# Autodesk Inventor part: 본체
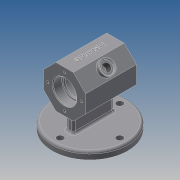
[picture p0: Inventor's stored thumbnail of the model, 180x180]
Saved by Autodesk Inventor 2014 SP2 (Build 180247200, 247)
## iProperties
Created: 2021-02
Part Number: 본체
Material: Generic
Document SubType Name: Modeling
Designer: kb542-10
Density: 1 g/cm^3
Appearance: Default
Author: kb542-10
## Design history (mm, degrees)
sketch "스케치1"
  geometry: L1 (11.995, -29.007)-(-12.03, -28.993); L2 (-12.03, -28.993)-(-29.007, -11.995); L3 (-29.007, -11.995)-(-28.993, 12.03); L4 (-28.993, 12.03)-(-11.995, 29.007); L5 (-11.995, 29.007)-(12.03, 28.993); L6 (12.03, 28.993)-(29.007, 11.995); L7 (29.007, 11.995)-(28.993, -12.03); L8 (28.993, -12.03)-(11.995, -29.007); 2 further points
  constraints: 16 end point, 1 coincident, 17 other
  dimensions: "d0" = 58 distance between parallel lines of L8 L4
extrude "돌출1" new body sketch "스케치1" stored distance "d1" = 70; taper "d2" = 0 deg
sketch "스케치2"
  geometry: L1 (12.03, 35)-(-11.995, 35) reference; L2 (-11.995, -35)-(12.03, -35) reference; L3 (29.007, 35)-(29.007, -35) reference; L4 (-28.993, 35)-(-28.993, -35) reference; L5 (0.018, 35)-(0.018, -35); L6 (16.018, 35)-(16.018, 23); L7 (16.018, 23)-(14.018, 23); L8 (14.018, 23)-(14.018, 20); L9 (14.018, 20)-(22.018, 20); L10 (22.018, 20)-(22.018, -20); L11 (22.018, -20)-(14.018, -20); L12 (14.018, -20)-(14.018, -23); L13 (14.018, -23)-(16.018, -23); L14 (16.018, -23)-(16.018, -35); L15 (16.018, 35)-(0.018, 35); L16 (16.018, -35)-(0.018, -35); 1 further point
  constraints: 24 end point, 7 parallel, 3 collinear, 3 perpendicular, 2 midpoint, 2 point on line
  dimensions: "d3" = 44 diameter of L10 L5; "d4" = 32 diameter of L6 L5; "d5" = 28 diameter of L8 L5; "d6" = 12 distance of L6.start L6.end; "d7" = 12 distance of L13.end L14.end; "d8" = 3 distance of L7.end L8.end; "d9" = 3 distance of L11.end L12.end
revolve "회전1" sketch "스케치2" stored, may be unused: angle "d10" = 90 deg
node "작업 평면1"
sketch "스케치3"
  geometry: C1 r 52 at (0, 0); 1 further point
  constraints: 1 centre point, 1 coincident
  dimensions: "d12" = 104 diameter of C1
extrude "돌출2" join sketch "스케치3" distance "d13" = 10; taper "d14" = 0 deg
sketch "스케치4"
  geometry: L1 (0, 52)-(0, -52); L2 (52, 0)-(-52, 0); L3 (5, 28)-(-5, 28); L4 (-5, 28)-(-5, -28); L5 (-5, -28)-(5, -28); L6 (5, -28)-(5, 28); A1 r 52 centre (0, 0) between (0, 52) and (0, -52) reference; 4 further points
  constraints: 12 end point, 6 midpoint, 4 point on circle, 2 parallel, 2 perpendicular, 1 horizontal, 1 horizontal alignment, 1 vertical, 1 vertical alignment
  dimensions: "d15" = 10 distance between parallel lines of L4 L6; "d16" = 56 distance between parallel lines of L5 L3
extrude "돌출3" join sketch "스케치4" stored distance "d17" = 10; taper "d18" = 0 deg
sketch "스케치11"
  geometry: L1 (0, 16.988)-(70, 16.988) reference; C1 r 10 at (35, -12.012); 1 further point
  constraints: 1 centre point, 1 coincident
  dimensions: "d47" = 20 diameter of C1
extrude "돌출6" join sketch "스케치11" distance "d48" = 5; taper "d49" = 0 deg
sketch "스케치12"
  geometry: C1 r 10 at (0, 0) reference; C2 r 8 at (0, 0)
  constraints: 1 centre point, 1 coincident
  dimensions: "d50" = 16 diameter of C2
extrude "돌출7" cut sketch "스케치12" distance "d51" = 2; taper "d52" = 0 deg
sketch "스케치13"
  geometry: C1 r 8 at (0, 0) reference; 1 further point
  constraints: 1 coincident
hole "구멍3" sketch "스케치13" at (0, 0) diameter "d53" = 10.917; stored, may be unused: countersink angle "d57" = 90 deg, drill point angle "d59" = 118 deg; dims "d54" = 15, "d55" = 4, "d56" = 2, "d58" = 8
sketch "스케치8"
  geometry: L1 (5, 28)-(5, -28) reference; L2 (5, -28)-(-5, -28) reference; L3 (-52, 0)-(52, 0); L4 (0, 52)-(0, -52); A1 r 52 centre (0, 0) between (-52, 0) and (52, 0) reference; A2 r 41 centre (0, 0) between (0, 41) and (-41, 0); 4 further points
  constraints: 8 point on circle, 4 end point, 4 midpoint, 4 point on line, 2 parallel, 1 centre point, 1 coincident
  dimensions: "d27" = 82 diameter of A2
hole "구멍1" sketch "스케치8" at (0, 41), (-41, 0), (0, -41), (41, 0) diameter "d28" = 9; stored, may be unused: countersink angle "d32" = 90 deg, drill point angle "d34" = 118 deg; dims "d29" = 6, "d30" = 4, "d31" = 2, "d33" = 8
sketch "스케치14" dims "d65" = 46
  geometry: C1 r 16 at (0, 0.018) reference; 6 further points
  constraints: 1 coincident, 1 horizontal alignment, 8 other
  dimensions: "d68" = 360 deg dimension on C1.centre point (23, 0.018) (derived)
hole "구멍4" sketch "스케치14" at (23, 0.018), (0, 23.018), (-23, 0.018), (0, -22.982) diameter "d70" = 3.242; stored, may be unused: countersink angle "d74" = 90 deg, drill point angle "d76" = 118 deg; dims "d71" = 8, "d72" = 4, "d73" = 2, "d75" = 10
sketch "스케치10"
  geometry: L1 (24.024, 0)-(0, 0) reference; L2 (-16.988, 0)-(-16.988, 70) reference; 2 further points
  constraints: 1 other
  dimensions: "d42" = 35 distance from line of L1 point (12.012, 35); "d43" = 29 distance from line of point (12.012, 35) L2
feature "엠보싱1" sketch "스케치10" dims "d44" = 1, "d45" = 0
chamfer "모따기1" distance "d60" = 1; stored, may be unused: second distance "d61" = 2, angle "d62" = 45 deg
fillet "모깎기1" dims "d63" = 3
fillet "모깎기2" dims "d64" = 3
node "솔리드1"
mirror "대칭1"
other parameters: "d11" = -62
